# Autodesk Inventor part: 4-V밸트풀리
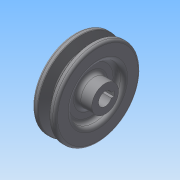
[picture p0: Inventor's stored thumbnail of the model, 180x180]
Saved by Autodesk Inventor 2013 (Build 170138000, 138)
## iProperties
Created: 2015-02
Part Number: 4-V밸트풀리
Material: 일반
Document SubType Name: Modeling
Designer: Administrator
Density: 1 g/cm^3
Author: Administrator
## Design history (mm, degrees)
sketch "스케치1"
  geometry: L1 (0, 0)-(-25, 0); L2 (-12, 21.5)-(-6, 21.5); L3 (-6, 21.5)-(-6, 35.2); L4 (-6, 35.2)-(-10.675, 35.2); L5 (-10.675, 35.2)-(-13.457, 26.1); L6 (-13.457, 26.1)-(-17.543, 26.1); L7 (-17.543, 26.1)-(-20.325, 35.2); L8 (-20.325, 35.2)-(-25, 35.2); L9 (-25, 35.2)-(-25, 21.5); L10 (-25, 21.5)-(-19, 21.5); L11 (-12, 21.5)-(-12, 11); L12 (-12, 11)-(0, 11); L13 (0, 11)-(0, 0); L14 (-19, 21.5)-(-19, 11); L15 (-19, 11)-(-25, 11); L16 (-25, 11)-(-25, 0); 2 further points
  constraints: 32 end point, 6 equal length, 6 parallel, 3 perpendicular, 2 collinear, 2 horizontal, 2 point on line, 2 vertical, 1 horizontal alignment, 1 vertical alignment
  dimensions: "d0" = 25 distance of L1.start L1.end; "d1" = 19 distance of L3.end L8.end; "d2" = 6 distance of L9.end L10.end; "d3" = 8 distance of point (-11.5, 32.5) point (-19.5, 32.5); "d4" = 34 deg angle of L5 L7; "d5" = 6 distance of L2.start L2.end (derived); "d6" = 22 diameter of L12 L1; "d7" = 43 diameter of L2 L1; "d8" = 65 diameter of point (-19.5, 32.5) L1; "d9" = 2.7 vertical distance of point (-19.5, 32.5) L7.end; "d10" = 6.4 vertical distance of L6.end point (-19.5, 32.5)
revolve "회전1" sketch "스케치1" stored, may be unused: angle "d11" = 90 deg
sketch "스케치2"
  geometry: L1 (-2, 5.123)-(-2, 7.3); L2 (-2, 7.3)-(2, 7.3); L3 (2, 7.3)-(2, 5.123); C1 r 11 at (0, 0) reference; A1 r 5.5 centre (0, 0) between (-2, 5.123) and (2, 5.123); 1 further point
  constraints: 6 end point, 2 parallel, 2 point on circle, 1 centre point, 1 coincident, 1 midpoint, 1 perpendicular, 1 vertical, 1 vertical alignment
  dimensions: "d12" = 11 diameter of A1; "d14" = 4 distance of L1.end L2.end; "d15" = 12.8 dimension on A1 L2
extrude "돌출1" cut sketch "스케치2" stored distance "d16" = 10; taper "d17" = 0 deg
fillet "모깎기1" dims "d18" = 3, "d19" = 1
fillet "모깎기2" dims "d20" = 0.5, "d21" = 2
node "솔리드1"
